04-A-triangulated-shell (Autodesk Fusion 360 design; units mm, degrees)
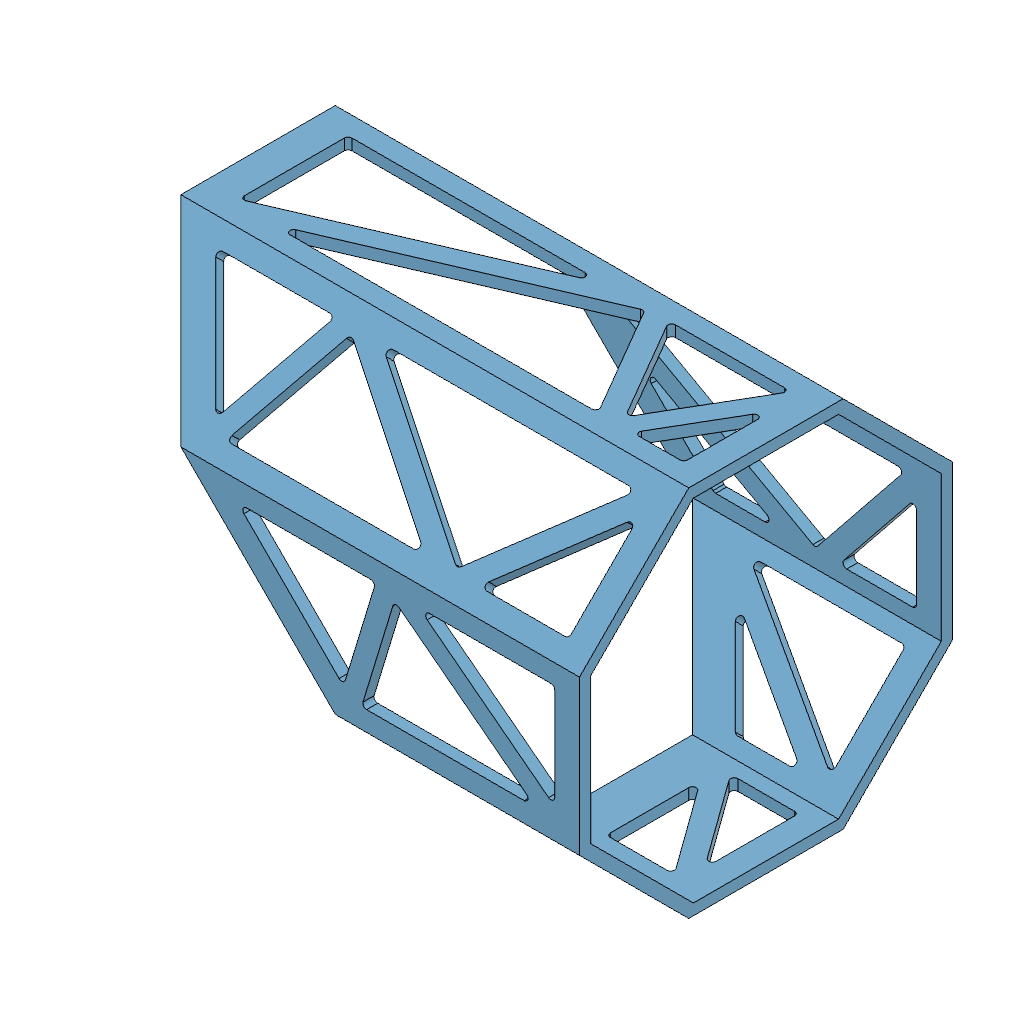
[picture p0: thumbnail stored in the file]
part number: 2026-11-02-20-17-55-344
part number: 2026-11-02-20-17-59-218
part number: 2026-11-02-20-17-59-224
parameter "bodyWidth" = 150 comment "Regular octagon across flats; corner diameter is larger."
parameter "bodyLength" = 260 comment "Overall straight length of the shared master blank."
parameter "splitAngle" = 45 comment "Keep this lesson angle at45 degrees."
parameter "faceGap" = 1 comment "Gap between the two printed joint faces."
parameter "wall" = 4.5 comment "Integrated shell and side brace radial thickness."
parameter "faceHalfWidth" = 31.066 (= "bodyWidth * ( sqrt(2) - 1 ) / 2") comment "Half-width of each outer planar facet."
parameter "memberWidth" = 8 comment "Nominal brace and corner chord width in a facet."
parameter "nodeHalfWidth" = 27.066 (= "faceHalfWidth - memberWidth / 2") comment "Chord centerlines measured from facet center."
parameter "jointNodeQ" = 7 comment "First truss skeleton row from the center joint plane."
parameter "endRim" = 10 comment "Uncut axial rim at each distant end."
parameter "endNodeX" = 124 (= "bodyLength / 2 - endRim + memberWidth / 2") comment "Last skeleton row before aperture inset."
parameter "apertureRadius" = 1.5 comment "Rounded internal corners at triangular openings."
parameter "spokeWidth" = 10 comment "Width of each deep bearing bulkhead spoke."
parameter "spokeDepth" = 18 comment "Bulkhead depth normal to the diagonal joint face."
parameter "carrierOD" = 52 comment "Outside of integrated A front bearing carrier."
parameter "rearCarrierClearance" = 46 comment "Internal carrier relief above front bearing shoulder."
parameter "tubeCornerChamfer" = 0.5 comment "Exposed outside octagon corner bevel."
parameter "tubeRimChamfer" = 0.3 comment "End rim and print-contact edge relief."
parameter "cordStation" = 125 (= "bodyLength / 2 - endRim / 2") comment "Load-test cord port center measured along body X."
parameter "bearingOD" = 22 comment "608 measured outside diameter."
parameter "bearingID" = 8 comment "608 bore."
parameter "bearingWidth" = 7 comment "608 width."
parameter "seatAllowance" = 0.2 comment "Trial DIAMETRAL clearance; choose with printed coupon."
parameter "seatDiameter" = 22.2 (= "bearingOD + seatAllowance") comment "Measured fit controls this."
parameter "coreOD" = 44 comment "Bearing holder outer diameter."
parameter "raceRelief" = 19.5 comment "Outer-ring shoulder opening; verify seals."
parameter "frontSeatDepth" = 7.1 comment "0.1 mm outer-ring axial allowance."
parameter "rearSeatDepth" = 7.2 comment "0.2 mm outer-ring axial float."
parameter "shoulder" = 3 comment "Backing behind each bearing seat."
parameter "supportSpacer" = 12 comment "Purchased metal M3 spacer length."
parameter "supportCircle" = 34 comment "Three M3 support bolts."
parameter "supportSpacerOD" = 6 comment "Purchased spacer outside diameter."
parameter "capThickness" = 3 comment "Both printed outer-ring retaining caps."
parameter "m3Clearance" = 3.3 comment "M3 through holes."
parameter "m4Clearance" = 4.3 comment "M4 through holes."
parameter "qFront" = 0.5 (= "faceGap / 2") comment "Front bearing starts at A mating face."
parameter "qFrontBack" = 10.6 (= "qFront + frontSeatDepth + shoulder") comment "End of integrated A holder."
parameter "qRearBase" = 22.6 (= "qFrontBack + supportSpacer") comment "Start of removable rear holder."
parameter "qRearBearing" = 25.6 (= "qRearBase + shoulder") comment "Rear bearing inner end."
parameter "qRearEnd" = 32.8 (= "qRearBearing + rearSeatDepth") comment "Rear holder outer end."
parameter "bearingSpacing" = 25.1 (= "qRearBearing - qFront") comment "Derived support-center spacing, not a bearing rating."
parameter "mountOD" = 76 comment "B mount and F flange outside diameter."
parameter "mountCircle" = 64 comment "Four M4 attachment holes."
parameter "mountOpening" = 50.3 comment "B through opening."
parameter "hubFace" = -23 comment "Metal hub flat mounting face."
parameter "adapterThickness" = 6 comment "F flange and metal compression sleeve length."
parameter "pilotDiameter" = 50 comment "F shallow centering pilot."
parameter "pilotInside" = 34 comment "Clearance around metal hub."
parameter "pilotHeight" = 2 comment "Short pilot only."
parameter "hubHoleSpacing" = 16 comment "Metal Sonic hub square hole spacing."
parameter "sleeveOD" = 8 comment "M4 metal compression sleeves."
parameter "sleeveAllowance" = 0.2 comment "Trial DIAMETRAL sleeve clearance."
parameter "shaftClearance" = 8.5 comment "F clearance hole; not a bearing."
parameter "nutAF" = 7.2 comment "M4 nominal 7 AF nut trial pocket."
parameter "nutDepth" = 4 comment "Open front M4 nut pocket."
parameter "rootRadius" = 1 comment "Hub-to-wall blend."
parameter "entryChamfer" = 0.4 comment "Assembly lead-in."
parameter "bedRelief" = 0.3 comment "Bed-contact edge allowance."
sketch "01 Master Octagon" plane through (0, 0, 0) normal (1, 0, 0) x axis (0, 0, -1)
  line L1 (31.066, 75) -> (75, 31.066)
  line L2 (-31.066, 75) -> (31.066, 75)
  line L3 (-75, 31.066) -> (-31.066, 75)
  line L4 (-75, -31.066) -> (-75, 31.066)
  line L5 (-31.066, -75) -> (-75, -31.066)
  line L6 (31.066, -75) -> (-31.066, -75)
  line L7 (75, -31.066) -> (31.066, -75)
  line L8 (75, 31.066) -> (75, -31.066)
  point P1 (0, 0)
  point P10 (0, 0)
  point P3 (31.066, 75)
  point P8 (31.066, -75)
  coincident P1 P10
  horizontal L2
  dimension "d59" distance P3 P8 = 150 (= "bodyWidth")
extrude "Extrude1" new body sketch "01 Master Octagon" distance 260 (= "bodyLength")
work_plane "WorkPlane1" RotateAngle 45 (= "splitAngle") ExtraOffset 0
split "Split1"
offset_faces "OffsetFaces1" distance -0.5 (= "-faceGap / 2")
offset_faces "OffsetFaces2" distance -0.5 (= "-faceGap / 2")
component_from_bodies "Body->Comp1"
component_from_bodies "Body->Comp2"
shell "Shell1" innerThickness 4.5 (= "wall")
shell "Shell1" innerThickness 4.5 (= "wall")
work_plane "WorkPlane1" RotateAngle -90 ExtraOffset 0
work_plane "WorkPlane2" AlongDistance 75 (= "bodyWidth / 2") ExtraOffset 0
sketch "A Facet 0 Triangle 1" plane through (0, 75, 0) normal (0, 1, 0) x axis (1, 0, 0)
  line L1 (-65.1005, -27.066) -> (-65.1005, 27.066)
  line L2 (60.9665, 27.066) -> (-65.1005, -27.066)
  line L3 (-65.1005, 27.066) -> (60.9665, 27.066)
  line L4 (-61.1005, -20.9953) -> (-61.1005, 23.066)
  line L5 (41.513, 23.066) -> (-61.1005, -20.9953)
  line L6 (-61.1005, 23.066) -> (41.513, 23.066)
  point P1 (0, 0)
  point P2 (-65.1005, 27.066)
  point P3 (-65.1005, -27.066)
  point P4 (60.9665, 27.066)
  dimension "d72" distance P1 P2 = 65.1005 (= "Linear Dimension-2")
  dimension "d73" distance P1 P2 = 27.066 (= "Linear Dimension-3")
  dimension "d74" distance P1 P3 = 65.1005 (= "Linear Dimension-4")
  dimension "d75" distance P1 P3 = 27.066 (= "Linear Dimension-5")
  dimension "d76" distance P1 P4 = 60.9665 (= "Linear Dimension-6")
  dimension "d77" distance P1 P4 = 27.066 (= "Linear Dimension-7")
  dimension "d78" = -4 (= "-memberWidth / 2")
extrude "Extrude1" cut sketch "A Facet 0 Triangle 1" profile of L5 L6 L4 against normal blind 4.7 (magnitude of "-( wall + 0.2 mm )")
sketch "A Facet 0 Triangle 2" plane through (0, 75, 0) normal (0, 1, 0) x axis (1, 0, 0)
  line L1 (60.9665, 27.066) -> (-65.1005, -27.066)
  line L2 (92.4832, -27.066) -> (60.9665, 27.066)
  line L3 (-65.1005, -27.066) -> (92.4832, -27.066)
  line L4 (59.2912, 21.9935) -> (-45.647, -23.066)
  line L5 (85.5258, -23.066) -> (59.2912, 21.9935)
  line L6 (-45.647, -23.066) -> (85.5258, -23.066)
  point P1 (0, 0)
  point P2 (-65.1005, -27.066)
  point P3 (60.9665, 27.066)
  point P4 (92.4832, -27.066)
  dimension "d81" distance P1 P2 = 65.1005 (= "Linear Dimension-2")
  dimension "d82" distance P1 P2 = 27.066 (= "Linear Dimension-3")
  dimension "d83" distance P1 P3 = 60.9665 (= "Linear Dimension-4")
  dimension "d84" distance P1 P3 = 27.066 (= "Linear Dimension-5")
  dimension "d85" distance P1 P4 = 92.4832 (= "Linear Dimension-6")
  dimension "d86" distance P1 P4 = 27.066 (= "Linear Dimension-7")
  dimension "d87" = 4 (= "memberWidth / 2")
extrude "Extrude2" cut sketch "A Facet 0 Triangle 2" profile of L5 L6 L4 against normal blind 4.7 (magnitude of "-( wall + 0.2 mm )")
sketch "A Facet 0 Triangle 3" plane through (0, 75, 0) normal (0, 1, 0) x axis (1, 0, 0)
  line L1 (92.4832, -27.066) -> (60.9665, 27.066)
  line L2 (124, 27.066) -> (92.4832, -27.066)
  line L3 (60.9665, 27.066) -> (124, 27.066)
  line L4 (92.4832, -19.1161) -> (67.924, 23.066)
  line L5 (117.0425, 23.066) -> (92.4832, -19.1161)
  line L6 (67.924, 23.066) -> (117.0425, 23.066)
  point P1 (0, 0)
  point P2 (60.9665, 27.066)
  point P3 (92.4832, -27.066)
  point P4 (124, 27.066)
  dimension "d90" distance P1 P2 = 60.9665 (= "Linear Dimension-2")
  dimension "d91" distance P1 P2 = 27.066 (= "Linear Dimension-3")
  dimension "d92" distance P1 P3 = 92.4832 (= "Linear Dimension-4")
  dimension "d93" distance P1 P3 = 27.066 (= "Linear Dimension-5")
  dimension "d94" distance P1 P4 = 124 (= "Linear Dimension-6")
  dimension "d95" distance P1 P4 = 27.066 (= "Linear Dimension-7")
  dimension "d96" = -4 (= "-memberWidth / 2")
extrude "Extrude3" cut sketch "A Facet 0 Triangle 3" profile of L5 L6 L4 against normal blind 4.7 (magnitude of "-( wall + 0.2 mm )")
sketch "A Facet 0 Triangle 4" plane through (0, 75, 0) normal (0, 1, 0) x axis (1, 0, 0)
  line L1 (124, 27.066) -> (92.4832, -27.066)
  line L2 (124, -27.066) -> (124, 27.066)
  line L3 (92.4832, -27.066) -> (124, -27.066)
  line L4 (120, 12.2459) -> (99.4407, -23.066)
  line L5 (120, -23.066) -> (120, 12.2459)
  line L6 (99.4407, -23.066) -> (120, -23.066)
  point P1 (0, 0)
  point P2 (92.4832, -27.066)
  point P3 (124, 27.066)
  point P4 (124, -27.066)
  dimension "d99" distance P1 P2 = 92.4832 (= "Linear Dimension-2")
  dimension "d100" distance P1 P2 = 27.066 (= "Linear Dimension-3")
  dimension "d101" distance P1 P3 = 124 (= "Linear Dimension-4")
  dimension "d102" distance P1 P3 = 27.066 (= "Linear Dimension-5")
  dimension "d103" distance P1 P4 = 124 (= "Linear Dimension-6")
  dimension "d104" distance P1 P4 = 27.066 (= "Linear Dimension-7")
  dimension "d105" = 4 (= "memberWidth / 2")
extrude "Extrude4" cut sketch "A Facet 0 Triangle 4" profile of L5 L6 L4 against normal blind 4.7 (magnitude of "-( wall + 0.2 mm )")
fillet "Fillet1" radius 1.5 (= "apertureRadius")
work_plane "WorkPlane3" RotateAngle -45 ExtraOffset 0
work_plane "WorkPlane4" AlongDistance 75 (= "bodyWidth / 2") ExtraOffset 0
sketch "A Facet 45 Triangle 1" plane through (0, 53.033, 53.033) normal (0, 0.7071, 0.7071) x axis (1, 0, 0)
  line L1 (-23.9949, -27.066) -> (-62.2721, 27.066)
  line L2 (-0.1814, 27.066) -> (-23.9949, -27.066)
  line L3 (-62.2721, 27.066) -> (-0.1814, 27.066)
  line L4 (-24.81, -18.9852) -> (-54.5447, 23.066)
  line L5 (-6.311, 23.066) -> (-24.81, -18.9852)
  line L6 (-54.5447, 23.066) -> (-6.311, 23.066)
  point P1 (0, 0)
  point P2 (-62.2721, 27.066)
  point P3 (-23.9949, -27.066)
  point P4 (-0.1814, 27.066)
  dimension "d114" distance P1 P2 = 62.2721 (= "Linear Dimension-2")
  dimension "d115" distance P1 P2 = 27.066 (= "Linear Dimension-3")
  dimension "d116" distance P1 P3 = 23.9949 (= "Linear Dimension-4")
  dimension "d117" distance P1 P3 = 27.066 (= "Linear Dimension-5")
  dimension "d118" distance P1 P4 = 0.1814 (= "Linear Dimension-6")
  dimension "d119" distance P1 P4 = 27.066 (= "Linear Dimension-7")
  dimension "d120" = -4 (= "-memberWidth / 2")
extrude "Extrude5" cut sketch "A Facet 45 Triangle 1" profile of L5 L6 L4 against normal blind 4.7 (magnitude of "-( wall + 0.2 mm )")
sketch "A Facet 45 Triangle 2" plane through (0, 53.033, 53.033) normal (0, 0.7071, 0.7071) x axis (1, 0, 0)
  line L1 (-0.1814, 27.066) -> (-23.9949, -27.066)
  line L2 (74.6684, -27.066) -> (-0.1814, 27.066)
  line L3 (-23.9949, -27.066) -> (74.6684, -27.066)
  line L4 (1.4863, 20.9235) -> (-17.8653, -23.066)
  line L5 (62.3117, -23.066) -> (1.4863, 20.9235)
  line L6 (-17.8653, -23.066) -> (62.3117, -23.066)
  point P1 (0, 0)
  point P2 (-23.9949, -27.066)
  point P3 (-0.1814, 27.066)
  point P4 (74.6684, -27.066)
  dimension "d123" distance P1 P2 = 23.9949 (= "Linear Dimension-2")
  dimension "d124" distance P1 P2 = 27.066 (= "Linear Dimension-3")
  dimension "d125" distance P1 P3 = 0.1814 (= "Linear Dimension-4")
  dimension "d126" distance P1 P3 = 27.066 (= "Linear Dimension-5")
  dimension "d127" distance P1 P4 = 74.6684 (= "Linear Dimension-6")
  dimension "d128" distance P1 P4 = 27.066 (= "Linear Dimension-7")
  dimension "d129" = 4 (= "memberWidth / 2")
extrude "Extrude6" cut sketch "A Facet 45 Triangle 2" profile of L5 L6 L4 against normal blind 4.7 (magnitude of "-( wall + 0.2 mm )")
sketch "A Facet 45 Triangle 3" plane through (0, 53.033, 53.033) normal (0, 0.7071, 0.7071) x axis (1, 0, 0)
  line L1 (74.6684, -27.066) -> (-0.1814, 27.066)
  line L2 (124, 27.066) -> (74.6684, -27.066)
  line L3 (-0.1814, 27.066) -> (124, 27.066)
  line L4 (74.1179, -21.7315) -> (12.1753, 23.066)
  line L5 (114.9429, 23.066) -> (74.1179, -21.7315)
  line L6 (12.1753, 23.066) -> (114.9429, 23.066)
  point P1 (0, 0)
  point P2 (-0.1814, 27.066)
  point P3 (74.6684, -27.066)
  point P4 (124, 27.066)
  dimension "d132" distance P1 P2 = 0.1814 (= "Linear Dimension-2")
  dimension "d133" distance P1 P2 = 27.066 (= "Linear Dimension-3")
  dimension "d134" distance P1 P3 = 74.6684 (= "Linear Dimension-4")
  dimension "d135" distance P1 P3 = 27.066 (= "Linear Dimension-5")
  dimension "d136" distance P1 P4 = 124 (= "Linear Dimension-6")
  dimension "d137" distance P1 P4 = 27.066 (= "Linear Dimension-7")
  dimension "d138" = -4 (= "-memberWidth / 2")
extrude "Extrude7" cut sketch "A Facet 45 Triangle 3" profile of L5 L6 L4 against normal blind 4.7 (magnitude of "-( wall + 0.2 mm )")
sketch "A Facet 45 Triangle 4" plane through (0, 53.033, 53.033) normal (0, 0.7071, 0.7071) x axis (1, 0, 0)
  line L1 (124, 27.066) -> (74.6684, -27.066)
  line L2 (124, -27.066) -> (124, 27.066)
  line L3 (74.6684, -27.066) -> (124, -27.066)
  line L4 (120, 16.7383) -> (83.7255, -23.066)
  line L5 (120, -23.066) -> (120, 16.7383)
  line L6 (83.7255, -23.066) -> (120, -23.066)
  point P1 (0, 0)
  point P2 (74.6684, -27.066)
  point P3 (124, 27.066)
  point P4 (124, -27.066)
  dimension "d141" distance P1 P2 = 74.6684 (= "Linear Dimension-2")
  dimension "d142" distance P1 P2 = 27.066 (= "Linear Dimension-3")
  dimension "d143" distance P1 P3 = 124 (= "Linear Dimension-4")
  dimension "d144" distance P1 P3 = 27.066 (= "Linear Dimension-5")
  dimension "d145" distance P1 P4 = 124 (= "Linear Dimension-6")
  dimension "d146" distance P1 P4 = 27.066 (= "Linear Dimension-7")
  dimension "d147" = 4 (= "memberWidth / 2")
extrude "Extrude8" cut sketch "A Facet 45 Triangle 4" profile of L5 L6 L4 against normal blind 4.7 (magnitude of "-( wall + 0.2 mm )")
fillet "Fillet2" radius 1.5 (= "apertureRadius")
work_plane "WorkPlane5" RotateAngle 0 ExtraOffset 0
work_plane "WorkPlane6" AlongDistance 75 (= "bodyWidth / 2") ExtraOffset 0
sketch "A Facet 90 Triangle 1" plane through (0, 0, 75) normal (0, 0, 1) x axis (1, 0, 0)
  line L1 (36.9655, -27.066) -> (-17.1665, 27.066)
  line L2 (53.4167, 27.066) -> (36.9655, -27.066)
  line L3 (-17.1665, 27.066) -> (53.4167, 27.066)
  line L4 (35.0777, -19.5214) -> (-7.5097, 23.066)
  line L5 (48.0205, 23.066) -> (35.0777, -19.5214)
  line L6 (-7.5097, 23.066) -> (48.0205, 23.066)
  point P1 (0, 0)
  point P2 (-17.1665, 27.066)
  point P3 (36.9655, -27.066)
  point P4 (53.4167, 27.066)
  dimension "d156" distance P1 P2 = 17.1665 (= "Linear Dimension-2")
  dimension "d157" distance P1 P2 = 27.066 (= "Linear Dimension-3")
  dimension "d158" distance P1 P3 = 36.9655 (= "Linear Dimension-4")
  dimension "d159" distance P1 P3 = 27.066 (= "Linear Dimension-5")
  dimension "d160" distance P1 P4 = 53.4167 (= "Linear Dimension-6")
  dimension "d161" distance P1 P4 = 27.066 (= "Linear Dimension-7")
  dimension "d162" = -4 (= "-memberWidth / 2")
extrude "Extrude9" cut sketch "A Facet 90 Triangle 1" profile of L5 L6 L4 against normal blind 4.7 (magnitude of "-( wall + 0.2 mm )")
sketch "A Facet 90 Triangle 2" plane through (0, 0, 75) normal (0, 0, 1) x axis (1, 0, 0)
  line L1 (53.4167, 27.066) -> (36.9655, -27.066)
  line L2 (124, -27.066) -> (53.4167, 27.066)
  line L3 (36.9655, -27.066) -> (124, -27.066)
  line L4 (55.5648, 20.3777) -> (42.3618, -23.066)
  line L5 (112.2115, -23.066) -> (55.5648, 20.3777)
  line L6 (42.3618, -23.066) -> (112.2115, -23.066)
  point P1 (0, 0)
  point P2 (36.9655, -27.066)
  point P3 (53.4167, 27.066)
  point P4 (124, -27.066)
  dimension "d165" distance P1 P2 = 36.9655 (= "Linear Dimension-2")
  dimension "d166" distance P1 P2 = 27.066 (= "Linear Dimension-3")
  dimension "d167" distance P1 P3 = 53.4167 (= "Linear Dimension-4")
  dimension "d168" distance P1 P3 = 27.066 (= "Linear Dimension-5")
  dimension "d169" distance P1 P4 = 124 (= "Linear Dimension-6")
  dimension "d170" distance P1 P4 = 27.066 (= "Linear Dimension-7")
  dimension "d171" = 4 (= "memberWidth / 2")
extrude "Extrude10" cut sketch "A Facet 90 Triangle 2" profile of L5 L6 L4 against normal blind 4.7 (magnitude of "-( wall + 0.2 mm )")
sketch "A Facet 90 Triangle 3" plane through (0, 0, 75) normal (0, 0, 1) x axis (1, 0, 0)
  line L1 (124, -27.066) -> (53.4167, 27.066)
  line L2 (124, 27.066) -> (124, -27.066)
  line L3 (53.4167, 27.066) -> (124, 27.066)
  line L4 (120, -18.9574) -> (65.2053, 23.066)
  line L5 (120, 23.066) -> (120, -18.9574)
  line L6 (65.2053, 23.066) -> (120, 23.066)
  point P1 (0, 0)
  point P2 (53.4167, 27.066)
  point P3 (124, -27.066)
  point P4 (124, 27.066)
  dimension "d174" distance P1 P2 = 53.4167 (= "Linear Dimension-2")
  dimension "d175" distance P1 P2 = 27.066 (= "Linear Dimension-3")
  dimension "d176" distance P1 P3 = 124 (= "Linear Dimension-4")
  dimension "d177" distance P1 P3 = 27.066 (= "Linear Dimension-5")
  dimension "d178" distance P1 P4 = 124 (= "Linear Dimension-6")
  dimension "d179" distance P1 P4 = 27.066 (= "Linear Dimension-7")
  dimension "d180" = -4 (= "-memberWidth / 2")
extrude "Extrude11" cut sketch "A Facet 90 Triangle 3" profile of L5 L6 L4 against normal blind 4.7 (magnitude of "-( wall + 0.2 mm )")
fillet "Fillet3" radius 1.5 (= "apertureRadius")
work_plane "WorkPlane7" RotateAngle 45 ExtraOffset 0
work_plane "WorkPlane8" AlongDistance 75 (= "bodyWidth / 2") ExtraOffset 0
sketch "A Facet 135 Triangle 1" plane through (0, -53.033, 53.033) normal (0, -0.7071, 0.7071) x axis (1, 0, 0)
  line L1 (82.0711, -27.066) -> (43.7939, 27.066)
  line L2 (124, 27.066) -> (82.0711, -27.066)
  line L3 (43.7939, 27.066) -> (124, 27.066)
  line L4 (82.2175, -20.3449) -> (51.5213, 23.066)
  line L5 (115.8422, 23.066) -> (82.2175, -20.3449)
  line L6 (51.5213, 23.066) -> (115.8422, 23.066)
  point P1 (0, 0)
  point P2 (43.7939, 27.066)
  point P3 (82.0711, -27.066)
  point P4 (124, 27.066)
  dimension "d189" distance P1 P2 = 43.7939 (= "Linear Dimension-2")
  dimension "d190" distance P1 P2 = 27.066 (= "Linear Dimension-3")
  dimension "d191" distance P1 P3 = 82.0711 (= "Linear Dimension-4")
  dimension "d192" distance P1 P3 = 27.066 (= "Linear Dimension-5")
  dimension "d193" distance P1 P4 = 124 (= "Linear Dimension-6")
  dimension "d194" distance P1 P4 = 27.066 (= "Linear Dimension-7")
  dimension "d195" = -4 (= "-memberWidth / 2")
extrude "Extrude12" cut sketch "A Facet 135 Triangle 1" profile of L5 L6 L4 against normal blind 4.7 (magnitude of "-( wall + 0.2 mm )")
sketch "A Facet 135 Triangle 2" plane through (0, -53.033, 53.033) normal (0, -0.7071, 0.7071) x axis (1, 0, 0)
  line L1 (124, 27.066) -> (82.0711, -27.066)
  line L2 (124, -27.066) -> (124, 27.066)
  line L3 (82.0711, -27.066) -> (124, -27.066)
  line L4 (120, 15.3697) -> (90.2289, -23.066)
  line L5 (120, -23.066) -> (120, 15.3697)
  line L6 (90.2289, -23.066) -> (120, -23.066)
  point P1 (0, 0)
  point P2 (82.0711, -27.066)
  point P3 (124, 27.066)
  point P4 (124, -27.066)
  dimension "d198" distance P1 P2 = 82.0711 (= "Linear Dimension-2")
  dimension "d199" distance P1 P2 = 27.066 (= "Linear Dimension-3")
  dimension "d200" distance P1 P3 = 124 (= "Linear Dimension-4")
  dimension "d201" distance P1 P3 = 27.066 (= "Linear Dimension-5")
  dimension "d202" distance P1 P4 = 124 (= "Linear Dimension-6")
  dimension "d203" distance P1 P4 = 27.066 (= "Linear Dimension-7")
  dimension "d204" = 4 (= "memberWidth / 2")
extrude "Extrude13" cut sketch "A Facet 135 Triangle 2" profile of L5 L6 L4 against normal blind 4.7 (magnitude of "-( wall + 0.2 mm )")
fillet "Fillet4" radius 1.5 (= "apertureRadius")
work_plane "WorkPlane9" RotateAngle 90 ExtraOffset 0
work_plane "WorkPlane10" AlongDistance 75 (= "bodyWidth / 2") ExtraOffset 0
sketch "A Facet 180 Triangle 1" plane through (0, -75, 0) normal (0, -1, 0) x axis (-1, 0, 0)
  line L1 (-84.8995, 27.066) -> (-84.8995, -27.066)
  line L2 (-124, -27.066) -> (-84.8995, 27.066)
  line L3 (-84.8995, -27.066) -> (-124, -27.066)
  line L4 (-88.8995, 14.697) -> (-88.8995, -23.066)
  line L5 (-116.1764, -23.066) -> (-88.8995, 14.697)
  line L6 (-88.8995, -23.066) -> (-116.1764, -23.066)
  point P1 (0, 0)
  point P2 (-84.8995, -27.066)
  point P3 (-84.8995, 27.066)
  point P4 (-124, -27.066)
  dimension "d213" distance P1 P2 = 84.8995 (= "Linear Dimension-2")
  dimension "d214" distance P1 P2 = 27.066 (= "Linear Dimension-3")
  dimension "d215" distance P1 P3 = 84.8995 (= "Linear Dimension-4")
  dimension "d216" distance P1 P3 = 27.066 (= "Linear Dimension-5")
  dimension "d217" distance P1 P4 = 124 (= "Linear Dimension-6")
  dimension "d218" distance P1 P4 = 27.066 (= "Linear Dimension-7")
  dimension "d219" = -4 (= "-memberWidth / 2")
extrude "Extrude14" cut sketch "A Facet 180 Triangle 1" profile of L5 L6 L4 against normal blind 4.7 (magnitude of "-( wall + 0.2 mm )")
sketch "A Facet 180 Triangle 2" plane through (0, -75, 0) normal (0, -1, 0) x axis (-1, 0, 0)
  line L1 (-124, -27.066) -> (-84.8995, 27.066)
  line L2 (-124, 27.066) -> (-124, -27.066)
  line L3 (-84.8995, 27.066) -> (-124, 27.066)
  line L4 (-120, -14.697) -> (-92.7231, 23.066)
  line L5 (-120, 23.066) -> (-120, -14.697)
  line L6 (-92.7231, 23.066) -> (-120, 23.066)
  point P1 (0, 0)
  point P2 (-84.8995, 27.066)
  point P3 (-124, -27.066)
  point P4 (-124, 27.066)
  dimension "d222" distance P1 P2 = 84.8995 (= "Linear Dimension-2")
  dimension "d223" distance P1 P2 = 27.066 (= "Linear Dimension-3")
  dimension "d224" distance P1 P3 = 124 (= "Linear Dimension-4")
  dimension "d225" distance P1 P3 = 27.066 (= "Linear Dimension-5")
  dimension "d226" distance P1 P4 = 124 (= "Linear Dimension-6")
  dimension "d227" distance P1 P4 = 27.066 (= "Linear Dimension-7")
  dimension "d228" = 4 (= "memberWidth / 2")
extrude "Extrude15" cut sketch "A Facet 180 Triangle 2" profile of L5 L6 L4 against normal blind 4.7 (magnitude of "-( wall + 0.2 mm )")
fillet "Fillet5" radius 1.5 (= "apertureRadius")
work_plane "WorkPlane11" RotateAngle 135 ExtraOffset 0
work_plane "WorkPlane12" AlongDistance 75 (= "bodyWidth / 2") ExtraOffset 0
sketch "A Facet 225 Triangle 1" plane through (0, -53.033, -53.033) normal (0, -0.7071, -0.7071) x axis (1, 0, 0)
  line L1 (43.7939, -27.066) -> (82.0711, 27.066)
  line L2 (124, 27.066) -> (43.7939, -27.066)
  line L3 (82.0711, 27.066) -> (124, 27.066)
  line L4 (59.6927, -11.51) -> (84.1416, 23.066)
  line L5 (110.9231, 23.066) -> (59.6927, -11.51)
  line L6 (84.1416, 23.066) -> (110.9231, 23.066)
  point P1 (0, 0)
  point P2 (82.0711, 27.066)
  point P3 (43.7939, -27.066)
  point P4 (124, 27.066)
  dimension "d237" distance P1 P2 = 82.0711 (= "Linear Dimension-2")
  dimension "d238" distance P1 P2 = 27.066 (= "Linear Dimension-3")
  dimension "d239" distance P1 P3 = 43.7939 (= "Linear Dimension-4")
  dimension "d240" distance P1 P3 = 27.066 (= "Linear Dimension-5")
  dimension "d241" distance P1 P4 = 124 (= "Linear Dimension-6")
  dimension "d242" distance P1 P4 = 27.066 (= "Linear Dimension-7")
  dimension "d243" = -4 (= "-memberWidth / 2")
extrude "Extrude16" cut sketch "A Facet 225 Triangle 1" profile of L5 L6 L4 against normal blind 4.7 (magnitude of "-( wall + 0.2 mm )")
sketch "A Facet 225 Triangle 2" plane through (0, -53.033, -53.033) normal (0, -0.7071, -0.7071) x axis (1, 0, 0)
  line L1 (124, 27.066) -> (43.7939, -27.066)
  line L2 (124, -27.066) -> (124, 27.066)
  line L3 (43.7939, -27.066) -> (124, -27.066)
  line L4 (120, 19.5406) -> (56.8709, -23.066)
  line L5 (120, -23.066) -> (120, 19.5406)
  line L6 (56.8709, -23.066) -> (120, -23.066)
  point P1 (0, 0)
  point P2 (43.7939, -27.066)
  point P3 (124, 27.066)
  point P4 (124, -27.066)
  dimension "d246" distance P1 P2 = 43.7939 (= "Linear Dimension-2")
  dimension "d247" distance P1 P2 = 27.066 (= "Linear Dimension-3")
  dimension "d248" distance P1 P3 = 124 (= "Linear Dimension-4")
  dimension "d249" distance P1 P3 = 27.066 (= "Linear Dimension-5")
  dimension "d250" distance P1 P4 = 124 (= "Linear Dimension-6")
  dimension "d251" distance P1 P4 = 27.066 (= "Linear Dimension-7")
  dimension "d252" = 4 (= "memberWidth / 2")
extrude "Extrude17" cut sketch "A Facet 225 Triangle 2" profile of L5 L6 L4 against normal blind 4.7 (magnitude of "-( wall + 0.2 mm )")
fillet "Fillet6" radius 1.5 (= "apertureRadius")
work_plane "WorkPlane13" RotateAngle 180 ExtraOffset 0
work_plane "WorkPlane14" AlongDistance 75 (= "bodyWidth / 2") ExtraOffset 0
sketch "A Facet 270 Triangle 1" plane through (0, 0, -75) normal (0, 0, -1) x axis (-1, 0, 0)
  line L1 (17.1665, 27.066) -> (-36.9655, -27.066)
  line L2 (-80.4828, -27.066) -> (17.1665, 27.066)
  line L3 (-36.9655, -27.066) -> (-80.4828, -27.066)
  line L4 (-5.7896, 9.7668) -> (-38.6224, -23.066)
  line L5 (-65.0169, -23.066) -> (-5.7896, 9.7668)
  line L6 (-38.6224, -23.066) -> (-65.0169, -23.066)
  point P1 (0, 0)
  point P2 (-36.9655, -27.066)
  point P3 (17.1665, 27.066)
  point P4 (-80.4828, -27.066)
  dimension "d261" distance P1 P2 = 36.9655 (= "Linear Dimension-2")
  dimension "d262" distance P1 P2 = 27.066 (= "Linear Dimension-3")
  dimension "d263" distance P1 P3 = 17.1665 (= "Linear Dimension-4")
  dimension "d264" distance P1 P3 = 27.066 (= "Linear Dimension-5")
  dimension "d265" distance P1 P4 = 80.4828 (= "Linear Dimension-6")
  dimension "d266" distance P1 P4 = 27.066 (= "Linear Dimension-7")
  dimension "d267" = -4 (= "-memberWidth / 2")
extrude "Extrude18" cut sketch "A Facet 270 Triangle 1" profile of L5 L6 L4 against normal blind 4.7 (magnitude of "-( wall + 0.2 mm )")
sketch "A Facet 270 Triangle 2" plane through (0, 0, -75) normal (0, 0, -1) x axis (-1, 0, 0)
  line L1 (-80.4828, -27.066) -> (17.1665, 27.066)
  line L2 (-124, 27.066) -> (-80.4828, -27.066)
  line L3 (17.1665, 27.066) -> (-124, 27.066)
  line L4 (-79.4759, -21.9343) -> (1.7007, 23.066)
  line L5 (-115.6521, 23.066) -> (-79.4759, -21.9343)
  line L6 (1.7007, 23.066) -> (-115.6521, 23.066)
  point P1 (0, 0)
  point P2 (17.1665, 27.066)
  point P3 (-80.4828, -27.066)
  point P4 (-124, 27.066)
  dimension "d270" distance P1 P2 = 17.1665 (= "Linear Dimension-2")
  dimension "d271" distance P1 P2 = 27.066 (= "Linear Dimension-3")
  dimension "d272" distance P1 P3 = 80.4828 (= "Linear Dimension-4")
  dimension "d273" distance P1 P3 = 27.066 (= "Linear Dimension-5")
  dimension "d274" distance P1 P4 = 124 (= "Linear Dimension-6")
  dimension "d275" distance P1 P4 = 27.066 (= "Linear Dimension-7")
  dimension "d276" = 4 (= "memberWidth / 2")
extrude "Extrude19" cut sketch "A Facet 270 Triangle 2" profile of L5 L6 L4 against normal blind 4.7 (magnitude of "-( wall + 0.2 mm )")
sketch "A Facet 270 Triangle 3" plane through (0, 0, -75) normal (0, 0, -1) x axis (-1, 0, 0)
  line L1 (-124, 27.066) -> (-80.4828, -27.066)
  line L2 (-124, -27.066) -> (-124, 27.066)
  line L3 (-80.4828, -27.066) -> (-124, -27.066)
  line L4 (-120, 15.7062) -> (-88.8307, -23.066)
  line L5 (-120, -23.066) -> (-120, 15.7062)
  line L6 (-88.8307, -23.066) -> (-120, -23.066)
  point P1 (0, 0)
  point P2 (-80.4828, -27.066)
  point P3 (-124, 27.066)
  point P4 (-124, -27.066)
  dimension "d279" distance P1 P2 = 80.4828 (= "Linear Dimension-2")
  dimension "d280" distance P1 P2 = 27.066 (= "Linear Dimension-3")
  dimension "d281" distance P1 P3 = 124 (= "Linear Dimension-4")
  dimension "d282" distance P1 P3 = 27.066 (= "Linear Dimension-5")
  dimension "d283" distance P1 P4 = 124 (= "Linear Dimension-6")
  dimension "d284" distance P1 P4 = 27.066 (= "Linear Dimension-7")
  dimension "d285" = -4 (= "-memberWidth / 2")
extrude "Extrude20" cut sketch "A Facet 270 Triangle 3" profile of L5 L6 L4 against normal blind 4.7 (magnitude of "-( wall + 0.2 mm )")
fillet "Fillet7" radius 1.5 (= "apertureRadius")
work_plane "WorkPlane15" RotateAngle 225 ExtraOffset 0
work_plane "WorkPlane16" AlongDistance 75 (= "bodyWidth / 2") ExtraOffset 0
sketch "A Facet 315 Triangle 1" plane through (0, 53.033, -53.033) normal (0, 0.7071, -0.7071) x axis (1, 0, 0)
  line L1 (-62.2721, -27.066) -> (-23.9949, 27.066)
  line L2 (25.3367, 27.066) -> (-62.2721, -27.066)
  line L3 (-23.9949, 27.066) -> (25.3367, 27.066)
  line L4 (-47.6674, -13.34) -> (-21.9244, 23.066)
  line L5 (11.2532, 23.066) -> (-47.6674, -13.34)
  line L6 (-21.9244, 23.066) -> (11.2532, 23.066)
  point P1 (0, 0)
  point P2 (-23.9949, 27.066)
  point P3 (-62.2721, -27.066)
  point P4 (25.3367, 27.066)
  dimension "d294" distance P1 P2 = 23.9949 (= "Linear Dimension-2")
  dimension "d295" distance P1 P2 = 27.066 (= "Linear Dimension-3")
  dimension "d296" distance P1 P3 = 62.2721 (= "Linear Dimension-4")
  dimension "d297" distance P1 P3 = 27.066 (= "Linear Dimension-5")
  dimension "d298" distance P1 P4 = 25.3367 (= "Linear Dimension-6")
  dimension "d299" distance P1 P4 = 27.066 (= "Linear Dimension-7")
  dimension "d300" = -4 (= "-memberWidth / 2")
extrude "Extrude21" cut sketch "A Facet 315 Triangle 1" profile of L5 L6 L4 against normal blind 4.7 (magnitude of "-( wall + 0.2 mm )")
sketch "A Facet 315 Triangle 2" plane through (0, 53.033, -53.033) normal (0, 0.7071, -0.7071) x axis (1, 0, 0)
  line L1 (25.3367, 27.066) -> (-62.2721, -27.066)
  line L2 (61.9093, -27.066) -> (25.3367, 27.066)
  line L3 (-62.2721, -27.066) -> (61.9093, -27.066)
  line L4 (24.1722, 21.6445) -> (-48.1886, -23.066)
  line L5 (54.3795, -23.066) -> (24.1722, 21.6445)
  line L6 (-48.1886, -23.066) -> (54.3795, -23.066)
  point P1 (0, 0)
  point P2 (-62.2721, -27.066)
  point P3 (25.3367, 27.066)
  point P4 (61.9093, -27.066)
  dimension "d303" distance P1 P2 = 62.2721 (= "Linear Dimension-2")
  dimension "d304" distance P1 P2 = 27.066 (= "Linear Dimension-3")
  dimension "d305" distance P1 P3 = 25.3367 (= "Linear Dimension-4")
  dimension "d306" distance P1 P3 = 27.066 (= "Linear Dimension-5")
  dimension "d307" distance P1 P4 = 61.9093 (= "Linear Dimension-6")
  dimension "d308" distance P1 P4 = 27.066 (= "Linear Dimension-7")
  dimension "d309" = 4 (= "memberWidth / 2")
extrude "Extrude22" cut sketch "A Facet 315 Triangle 2" profile of L5 L6 L4 against normal blind 4.7 (magnitude of "-( wall + 0.2 mm )")
sketch "A Facet 315 Triangle 3" plane through (0, 53.033, -53.033) normal (0, 0.7071, -0.7071) x axis (1, 0, 0)
  line L1 (61.9093, -27.066) -> (25.3367, 27.066)
  line L2 (124, 27.066) -> (61.9093, -27.066)
  line L3 (25.3367, 27.066) -> (124, 27.066)
  line L4 (62.6909, -21.0779) -> (32.8665, 23.066)
  line L5 (113.325, 23.066) -> (62.6909, -21.0779)
  line L6 (32.8665, 23.066) -> (113.325, 23.066)
  point P1 (0, 0)
  point P2 (25.3367, 27.066)
  point P3 (61.9093, -27.066)
  point P4 (124, 27.066)
  dimension "d312" distance P1 P2 = 25.3367 (= "Linear Dimension-2")
  dimension "d313" distance P1 P2 = 27.066 (= "Linear Dimension-3")
  dimension "d314" distance P1 P3 = 61.9093 (= "Linear Dimension-4")
  dimension "d315" distance P1 P3 = 27.066 (= "Linear Dimension-5")
  dimension "d316" distance P1 P4 = 124 (= "Linear Dimension-6")
  dimension "d317" distance P1 P4 = 27.066 (= "Linear Dimension-7")
  dimension "d318" = -4 (= "-memberWidth / 2")
extrude "Extrude23" cut sketch "A Facet 315 Triangle 3" profile of L5 L6 L4 against normal blind 4.7 (magnitude of "-( wall + 0.2 mm )")
sketch "A Facet 315 Triangle 4" plane through (0, 53.033, -53.033) normal (0, 0.7071, -0.7071) x axis (1, 0, 0)
  line L1 (124, 27.066) -> (61.9093, -27.066)
  line L2 (124, -27.066) -> (124, 27.066)
  line L3 (61.9093, -27.066) -> (124, -27.066)
  line L4 (120, 18.272) -> (72.5843, -23.066)
  line L5 (120, -23.066) -> (120, 18.272)
  line L6 (72.5843, -23.066) -> (120, -23.066)
  point P1 (0, 0)
  point P2 (61.9093, -27.066)
  point P3 (124, 27.066)
  point P4 (124, -27.066)
  dimension "d321" distance P1 P2 = 61.9093 (= "Linear Dimension-2")
  dimension "d322" distance P1 P2 = 27.066 (= "Linear Dimension-3")
  dimension "d323" distance P1 P3 = 124 (= "Linear Dimension-4")
  dimension "d324" distance P1 P3 = 27.066 (= "Linear Dimension-5")
  dimension "d325" distance P1 P4 = 124 (= "Linear Dimension-6")
  dimension "d326" distance P1 P4 = 27.066 (= "Linear Dimension-7")
  dimension "d327" = 4 (= "memberWidth / 2")
extrude "Extrude24" cut sketch "A Facet 315 Triangle 4" profile of L5 L6 L4 against normal blind 4.7 (magnitude of "-( wall + 0.2 mm )")
fillet "Fillet8" radius 1.5 (= "apertureRadius")
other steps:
base_feature "Base Feature1" bodies "A Housing print"
base_feature "Base Feature1" bodies "B Moving Body print"
create_component "CreateComponent1"
reparent_decal "ReparentDecal1"
remove_body "RemoveBody1"
create_component "CreateComponent2"
reparent_decal "ReparentDecal2"
remove_body "RemoveBody2"
named bodies: "A Housing print", "B Moving Body print"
